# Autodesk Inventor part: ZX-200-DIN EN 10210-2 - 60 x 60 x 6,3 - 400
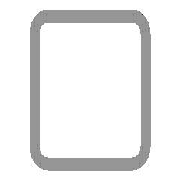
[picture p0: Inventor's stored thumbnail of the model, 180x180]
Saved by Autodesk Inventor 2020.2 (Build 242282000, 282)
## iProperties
Manager: www.cadconsulting.pl
Company: Fabian Stasiak CAD Consulting
IsCustomPart: 1
Created: 2015-02
Part Number: ZX-200-DIN EN 10210-2 - 60 x 60 x 6,3 - 400
Material: Stal, miękka
Description: Rura
Document SubType Name: Modeling
Standard: DIN EN 10210-2
Designer: F.Stasiak
Standard Revision: 2006-07
Standards Organization: DIN
Language: pl-PL
Size Designation: 60 x 60 x 6,3 - 400
Categories: <MemberInstance><Categories><Category DisplayName="Kształtowniki konstrukcyjne" InternalName="089c4875-fa83-4c05-b084-43b9cc11f5ed" Mnemonic="GRDR"><CategoryPar
Stock Number: 60 x 60 x 6,3
Density: 7.85 g/cm^3
Appearance: Częściowo polerowany
Catalog Web Link: www.expertbooks.pl
G_L: 400,000 mm
Author: F.Stasiak
Subject: Zbiór ćwiczeń. Autodesk Inventor 2020. Kurs Professional
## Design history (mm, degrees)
node "Start plane"
node "End plane"
sketch "Szkic"
  geometry: L1 (-30, -20.55)-(-30, 20.55); L2 (-20.55, 30)-(20.55, 30); L3 (30, 20.55)-(30, -20.55); L4 (20.55, -30)-(-20.55, -30); L5 (-20.55, 23.7)-(20.55, 23.7); L6 (23.7, 20.55)-(23.7, -20.55); L7 (20.55, -23.7)-(-20.55, -23.7); L8 (-23.7, -20.55)-(-23.7, 20.55); L9 (0, 37.102)-(0, -37.102) reference; L10 (-23.102, 0)-(23.102, 0) reference; A1 r 9.45 centre (-20.55, -20.55) between (-30, -20.55) and (-20.55, -30); A2 r 9.45 centre (-20.55, 20.55) between (-20.55, 30) and (-30, 20.55); A3 r 9.45 centre (20.55, 20.55) between (30, 20.55) and (20.55, 30); A4 r 9.45 centre (20.55, -20.55) between (20.55, -30) and (30, -20.55); A5 r 3.15 centre (-20.55, 20.55) between (-20.55, 23.7) and (-23.7, 20.55); A6 r 3.15 centre (20.55, 20.55) between (23.7, 20.55) and (20.55, 23.7); A7 r 3.15 centre (20.55, -20.55) between (20.55, -23.7) and (23.7, -20.55); A8 r 3.15 centre (-20.55, -20.55) between (-23.7, -20.55) and (-20.55, -23.7)
  constraints: 16 end point, 16 point on circle, 8 centre point, 8 tangent, 4 parallel, 3 equal radius, 2 perpendicular, 7 other
  dimensions: "d7" = 9.45 radius of A1 (= G_IR); "d10" = 60 distance between parallel lines of L2 L4 (= G_H); "d11" = 60 distance between parallel lines of L1 L3 (= G_W); "d12" = 6.3 distance between parallel lines of L3 L6 (= G_T); "d15" = 30 distance between parallel lines of L2 L10 (= 0.5 x d10); "d16" = 30 distance between parallel lines of L9 L3 (= 0.5 x d11)
extrude "Bryła" new body sketch "Szkic" stored distance "d3" = 400 (= G_L); taper "d4" = 0 deg
node "Driven Length"
  sketch "Sketch3"
    geometry: L1 (0, 0)-(10, 0) reference
    constraints: 2 end point, 1 horizontal
  workplane "Work Plane3"
  sketch "Sketch4"
    geometry: L1 (-2, 0)-(12, 0) reference; L2 (-2, 400)-(12, 400) reference
    dimensions: "d18" = 400 distance between parallel lines of L1 L2 (derived)
body "Solid1"
other parameters: "G_W" = 60 [user parameter; used in 1 equation term], "G_H" = 60 [user parameter; used in 1 equation term], "G_T" = 6.3 [user parameter; used in 1 equation term], "G_IR" = 9.45 [user parameter; used in 1 equation term], "G_L" = 400 (= d18) [user parameter; used in 1 equation term], "G_OFFSET_START" = 0 [user parameter; used in 1 equation term], "G_OFFSET_END" = 0 [user parameter; used in 1 equation term], "d13" = 0 (computed from G_OFFSET_START), "d17" = 90 deg
